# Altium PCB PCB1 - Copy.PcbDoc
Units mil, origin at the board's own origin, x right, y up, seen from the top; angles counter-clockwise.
Board outline 2362.2 x 3937.01 mil, 4 copper layers (Signal 1, GND 1, GND 2, Signal 2), stack 23.756 mil thick; 36 components, 44 nets, 223 pads, 235 vias.
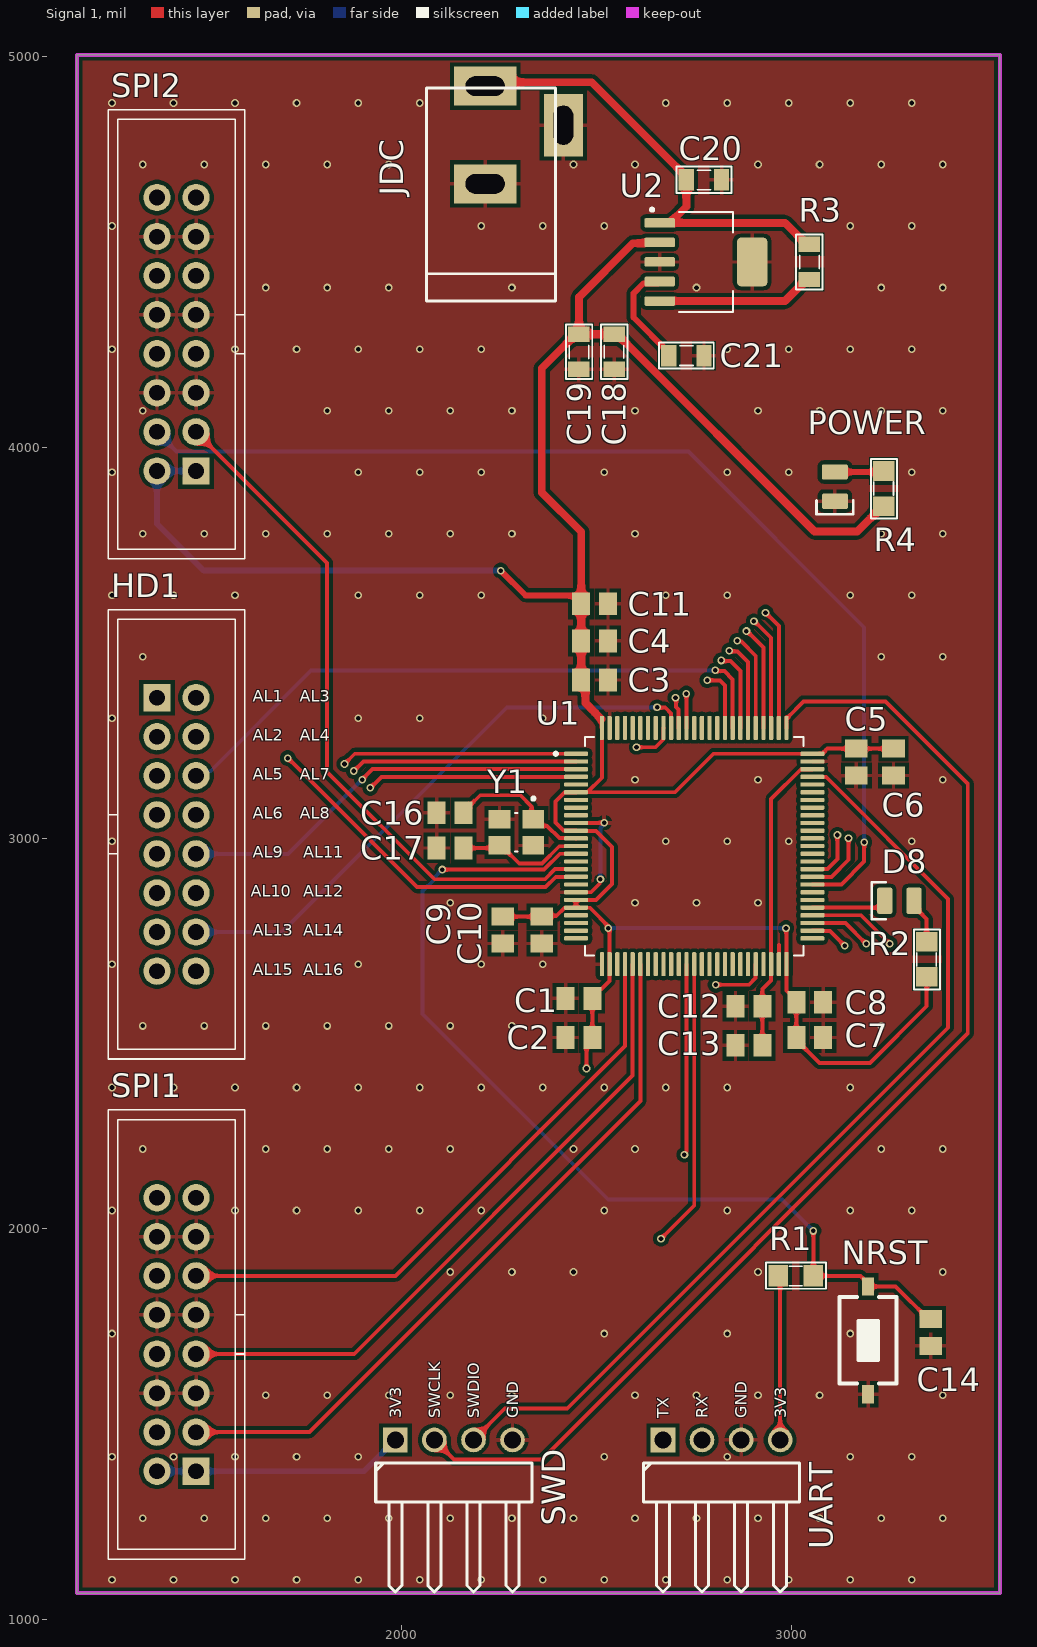
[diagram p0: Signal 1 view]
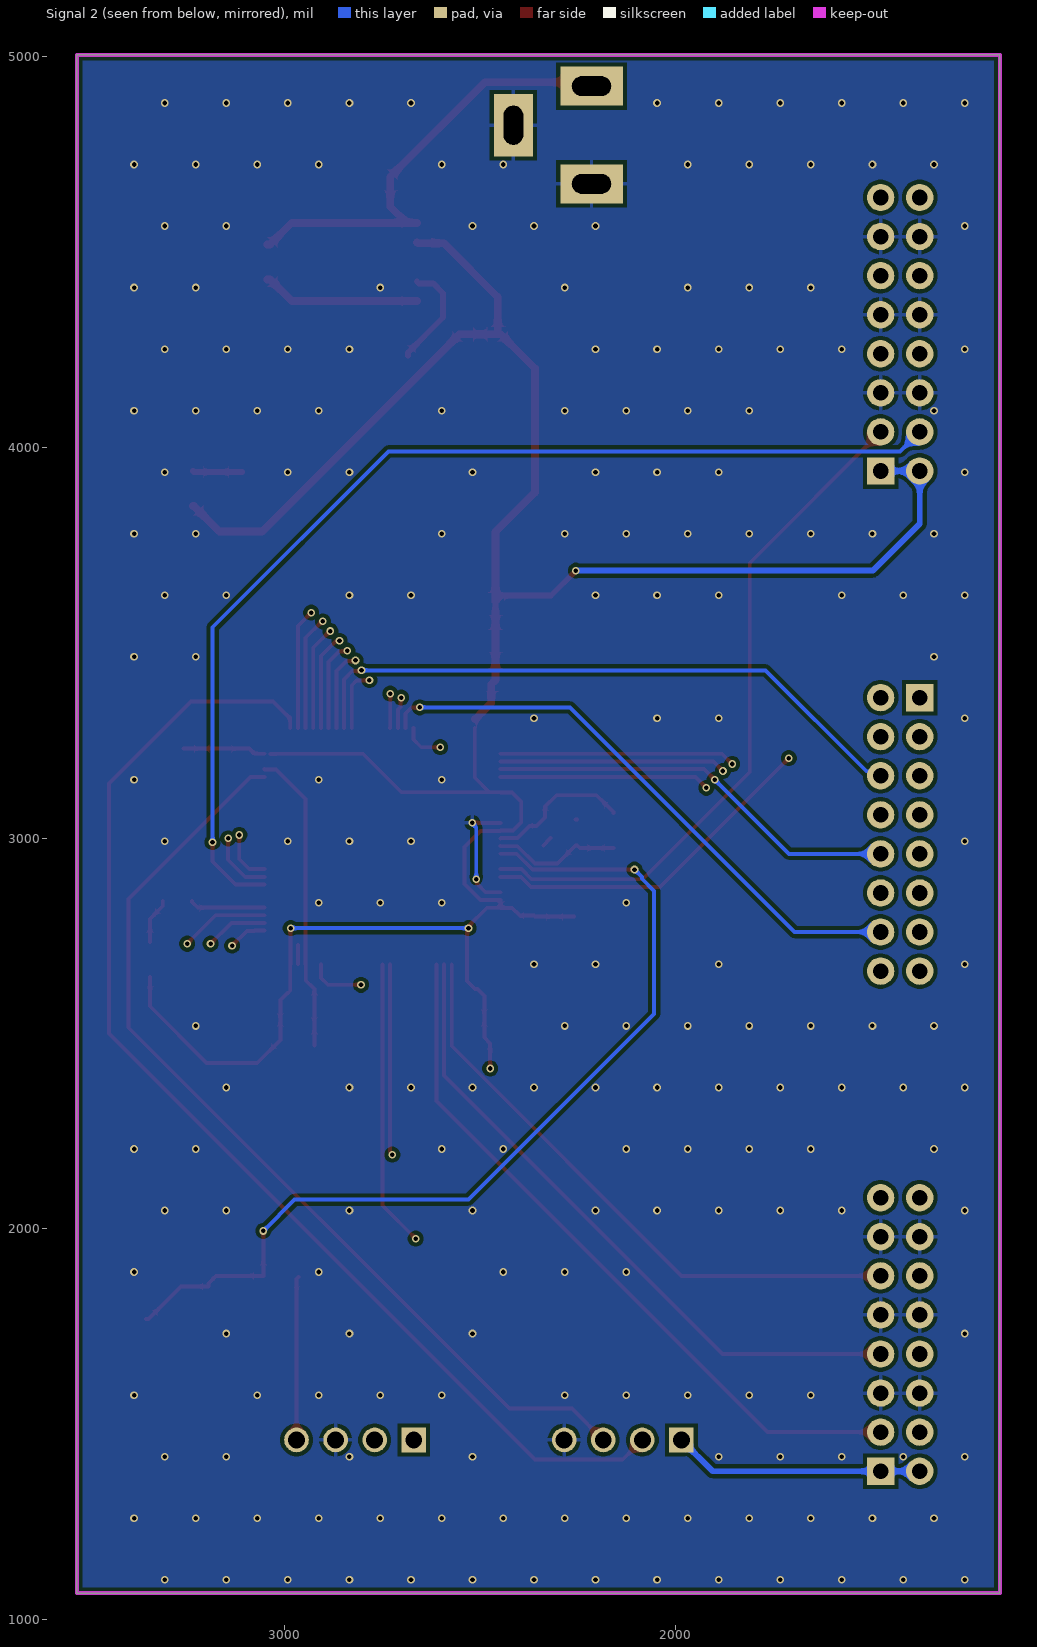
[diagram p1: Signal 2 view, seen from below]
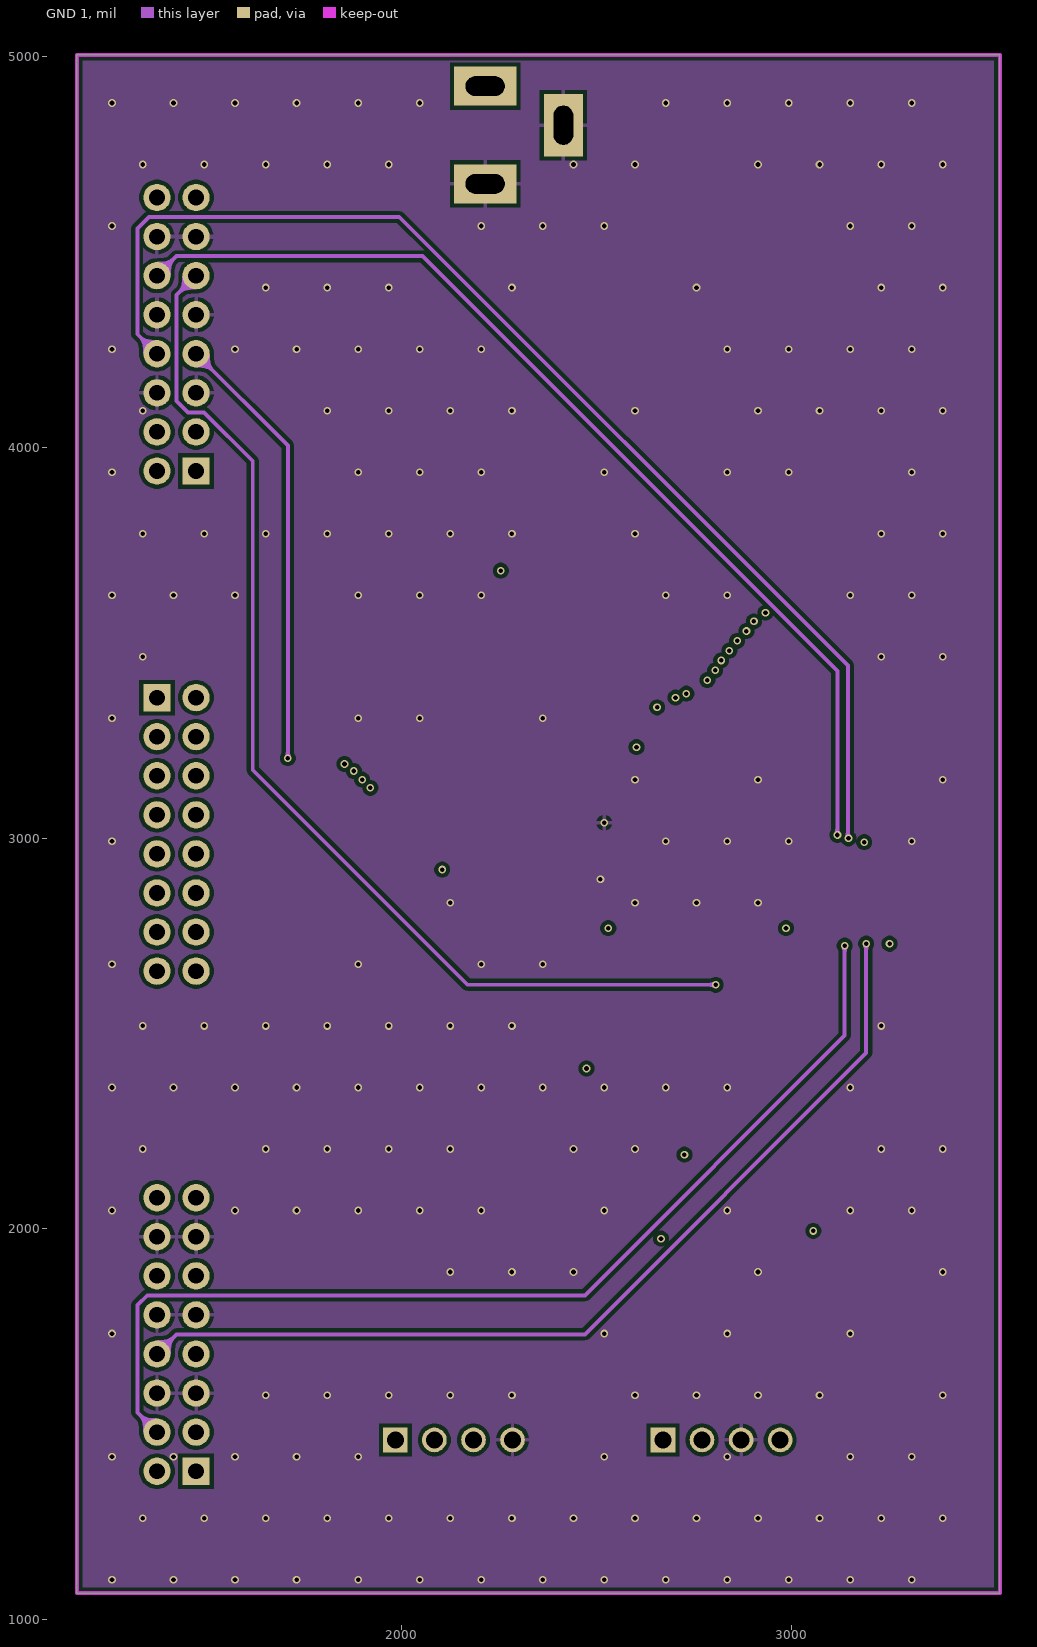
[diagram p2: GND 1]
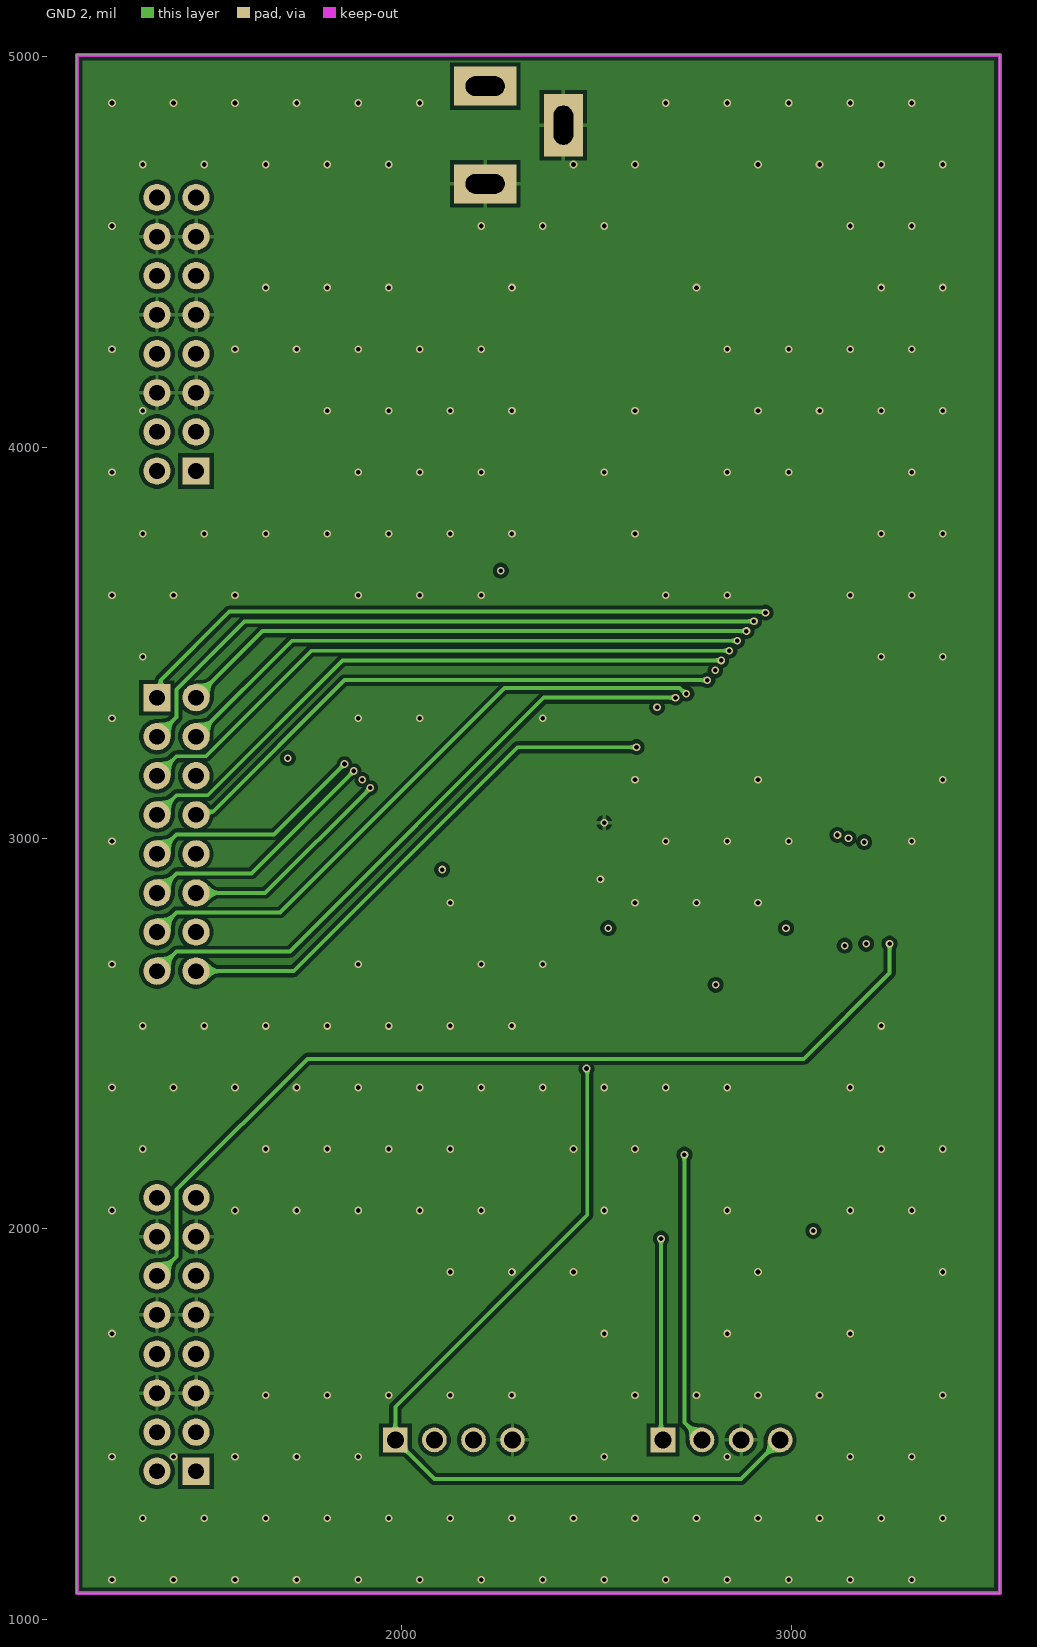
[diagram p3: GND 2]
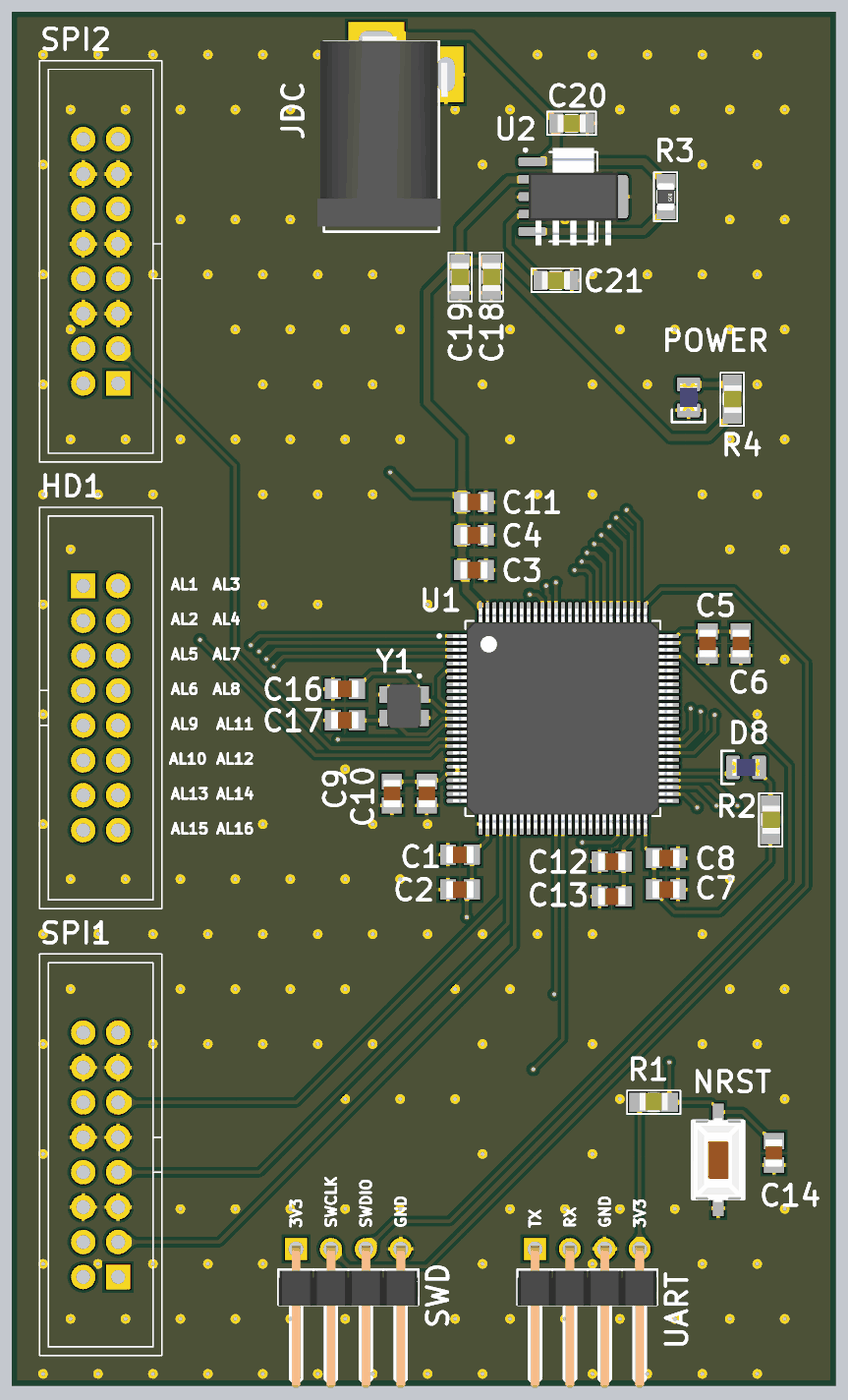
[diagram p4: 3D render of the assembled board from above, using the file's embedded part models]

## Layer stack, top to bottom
Top Solder: solder mask 0.4, Solder Resist, Dk 3.5
Signal 1: signal copper 1.378
Dielectric 2: prepreg 2.8, PP-006, Dk 4.1
GND 1: signal copper 1.4
Dielectric 1: dielectric 12.6, FR-4, Dk 4.8
GND 2: signal copper 1.4
Dielectric 3: prepreg 2.8, PP-006, Dk 4.1
Signal 2: signal copper 1.378
Bottom Solder: solder mask 0.4, Solder Resist, Dk 3.5

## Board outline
1170,1067.99 1170,5005 3532.2,5005 3532.2,1067.99

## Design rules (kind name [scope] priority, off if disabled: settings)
Clearance [All] p1: gap=10 ignorepadtopadclearanceinfootprint=TRUE except(5: Arc-Arc Arc-Track Arc-SMDPad Track-Track Track-SMDPad SMDPad-SMDPad)
PolygonConnect [All] p1: connectstyle=Relief reliefconductorwidth=10 reliefentries=4 polygonreliefangle="90 Angle" airgapwidth=10
RoutingVias [All] p1: holewidth=11.81 width=19.68 viastyle="Through Hole" minholewidth=7.87 minwidth=11.81 maxholewidth=28 maxwidth=50.28
SolderMaskExpansion [All] p1: expansion=4 istentingtop=FALSE
UnRoutedNet [All] p1: checkbadconnections=TRUE
Width [All] p1: maxlimit=50 minlimit=10 preferedwidth=10 minimp=50.000000 maximp=50.000000 favimp=50.000000
29 further rules are at their usual default settings.

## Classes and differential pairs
component class POWER: C18 C19 C20 C21 JDC POWER R3 R4 U2
component class MCU: C1 C2 C3 C4 C5 C6 C7 C8 C9 C10 C11 C12 C13 C14 C16 C17 D8 HD1 NRST R1 R2 SPI1 spi1 SPI2 SWD U1 UART Y1

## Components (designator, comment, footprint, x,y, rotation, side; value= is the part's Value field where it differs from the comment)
C1 "100nF" CAPC2012X145N 2455,2590 r0 top
C2 "100nF" CAPC2012X145N 2455,2490 r0 top
C3 "100nF" CAPC2012X145N 2495,3405 r180 top
C4 "100nF" CAPC2012X145N 2495,3505 r180 top
C5 "100nF" CAPC2012X145N 3165,3195 r90 top
C6 "100nF" CAPC2012X145N 3260,3195 r90 top
C7 "100nF" CAPC2012X145N 3045.71,2490 r180 top
C8 "100nF" CAPC2012X145N 3045.71,2580 r180 top
C9 "100nF" CAPC2012X145N 2260,2765 r90 top
C10 "100nF" CAPC2012X145N 2360,2765 r90 top
C11 "4.7uF" CAPC2012X145N 2495,3600 r180 top
C12 "2.2uF" CAPC2012X145N 2890,2570 r0 top
C13 "2.2uF" CAPC2012X145N 2890,2470 r0 top
C14 "100nF" CAPC2012X145N 3355,1735 r90 top
C16 "10pF" CAPC2012X145N 2125,3065 r0 top
C17 "10pF" CAPC2012X145N 2125,2975 r0 top
C18 "1uF" CAP_0805 2545,4245 r90 top value=33p
C19 "1uF" CAP_0805 2455,4245 r90 top value=33p
C20 "1uF" CAP_0805 2775,4685 r180 top value=33p
C21 "1uF" CAP_0805 2730,4235 r180 top value=33p
D8 "BLUE" LED_0805_BLUE 3275,2840 r0 top
HD1 "IDC 8X2" IDC16 1375,3360 r270 top value="Header 5x2"
JDC "Jac DC" DC-IN 2315,4800 r90 top
NRST "SW-SMD" SW-SMD 3195,1715 r270 top
POWER "BLUE" LED_0805_BLUE 3110,3900 r90 top
R1 "10K" SM-0805 3010,1880 r180 top value=1K
R2 "1K" SM-0805 3345,2690 r90 top
R3 "0R" RES-SMD-0805 3045,4475 r270 top
R4 "1K" SM-0805 3235,3895 r90 top
SPI1 "IDC 8X2" IDC16 1475,1380 r90 top value="Header 5x2"
SPI2 "IDC 8X2" IDC16 1475,3940 r90 top value="Header 5x2"
SWD "JP4" JP4-D1C 2335,1360 r0 top
U1 "STM32H743VIT6" QFP50P1600X1600X160-100N 2750,2980 r0 top
U2 "TPS73733DCQ" SOT127P706X180-6N 2780,4475 r0 top
UART "JP4" JP4-D1C 3020,1360 r0 top
Y1 "25MHz" XTAL_ABM8G-25.000MHZ-B4Y-T 2295,3015 r270 top

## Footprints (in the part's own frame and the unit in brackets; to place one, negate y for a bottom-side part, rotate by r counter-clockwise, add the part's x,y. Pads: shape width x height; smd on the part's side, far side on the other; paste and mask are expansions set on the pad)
CAP_0805 [mil]
  rect 39.37x55 smd: 1(-45,0) 2(45,0)
  silkscreen extent -70,-34 70,33, body extent -40,-25 40,25, height 24
CAPC2012X145N [mm]
  rect 1.17x1.47 smd: 1(-0.871,0) 2(0.871,0)
  body extent -1,-0.63 1,0.63, height 1.45
DC-IN [mil] "Jac DC input"
  rect 100x160 hole 50 slot 100 at 90 deg: 1(125,100) 2(-125,100)
  rect 160x100 hole 50 slot 100 at 0 deg: 3(25,-100)
  silkscreen extent -425,-80 120,250, body extent -410,-105 134,269, height 434
IDC16 [mil]
  rect 70x70 hole 40: 1(0,0)
  round 70 hole 40: 2(0,100) 3(100,0) 4(100,100) 5(200,0) 6(200,100) 7(300,0) 8(300,100) 9(400,0) 10(400,100) 11(500,0) 12(500,100) 13(600,0) 14(600,100) 15(700,0) 16(700,100)
  silkscreen extent -225,-125 925,225, body extent -225,-125 926,225, height 358
JP4-D1C [mm] "4 pins, 1 row, right angled, gold plating"
  rect 1.6x1.6 hole 1.1: 1(-8.89,2.54)
  round 1.6 hole 1.1: 2(-6.35,2.54) 3(-3.81,2.54) 4(-1.27,2.54)
  silkscreen extent -10.16,-7.34 0,1.04, body extent -10.16,-7.57 0,2.79, height 2.54
LED_0805_BLUE [mm]
  rrect25% 1x1.7 smd: A(0.95,0) K(-0.95,0)
  silkscreen extent -1.8,-1.2 -0.9,1.2, body extent -1,-0.63 1,0.63, height 1.12
QFP50P1600X1600X160-100N [mm]
  rrect50% 1.56x0.28 smd: 1(-7.68,6) 2(-7.68,5.5) 3(-7.68,5) 4(-7.68,4.5) 5(-7.68,4) 6(-7.68,3.5) 7(-7.68,3) 8(-7.68,2.5) 9(-7.68,2) 10(-7.68,1.5) 11(-7.68,1) 12(-7.68,0.5) 13(-7.68,0) 14(-7.68,-0.5) 15(-7.68,-1) 16(-7.68,-1.5) 17(-7.68,-2) 18(-7.68,-2.5) 19(-7.68,-3) 20(-7.68,-3.5) 21(-7.68,-4) 22(-7.68,-4.5) 23(-7.68,-5) 24(-7.68,-5.5) 25(-7.68,-6) 51(7.68,-6) 52(7.68,-5.5) 53(7.68,-5) 54(7.68,-4.5) 55(7.68,-4) 56(7.68,-3.5) 57(7.68,-3) 58(7.68,-2.5) 59(7.68,-2) 60(7.68,-1.5) 61(7.68,-1) 62(7.68,-0.5) 63(7.68,0) 64(7.68,0.5) 65(7.68,1) 66(7.68,1.5) 67(7.68,2) 68(7.68,2.5) 69(7.68,3) 70(7.68,3.5) 71(7.68,4) 72(7.68,4.5) 73(7.68,5) 74(7.68,5.5) 75(7.68,6)
  rrect50% 0.28x1.56 smd: 26(-6,-7.68) 27(-5.5,-7.68) 28(-5,-7.68) 29(-4.5,-7.68) 30(-4,-7.68) 31(-3.5,-7.68) 32(-3,-7.68) 33(-2.5,-7.68) 34(-2,-7.68) 35(-1.5,-7.68) 36(-1,-7.68) 37(-0.5,-7.68) 38(0,-7.68) 39(0.5,-7.68) 40(1,-7.68) 41(1.5,-7.68) 42(2,-7.68) 43(2.5,-7.68) 44(3,-7.68) 45(3.5,-7.68) 46(4,-7.68) 47(4.5,-7.68) 48(5,-7.68) 49(5.5,-7.68) 50(6,-7.68) 76(6,7.68) 77(5.5,7.68) 78(5,7.68) 79(4.5,7.68) 80(4,7.68) 81(3.5,7.68) 82(3,7.68) 83(2.5,7.68) 84(2,7.68) 85(1.5,7.68) 86(1,7.68) 87(0.5,7.68) 88(0,7.68) 89(-0.5,7.68) 90(-1,7.68) 91(-1.5,7.68) 92(-2,7.68) 93(-2.5,7.68) 94(-3,7.68) 95(-3.5,7.68) 96(-4,7.68) 97(-4.5,7.68) 98(-5,7.68) 99(-5.5,7.68) 100(-6,7.68)
  silkscreen extent -9.1,-7.1 7.1,7.1, body extent -8,-8 8,8, height 1.6
RES-SMD-0805 [mil]
  rect 39.37x55 smd: 1(-45,0) 2(45,0)
  silkscreen extent -70,-34 70,33, body extent -39,-25 39,25, height 31
SM-0805 [mil] "Compoment SMD 80x50mil"
  rect 50x55 smd: 1(-45,0) 2(45,0)
  silkscreen extent -77,-34 76,33, body extent -40,-27 40,23, height 24
SOT127P706X180-6N [mm]
  rrect25% 1.97x0.62 smd: 1(-3.005,2.54) 2(-3.005,1.27) 3(-3.005,0) 4(-3.005,-1.27) 5(-3.005,-2.54)
  rrect25% 1.97x3.16 smd: 6(3.005,0)
  silkscreen extent -3.6,-3.25 1.75,3.5, body extent -3.25,-3.53 3.25,3.53, height 1.8
SW-SMD [mm] "Switch SMD type"
  rect 1.2x0.8 smd: 1(-3.5,0) 2(3.5,0)
  silkscreen extent -2.82,-1.85 2.82,1.85, body extent -3.05,-1.85 3.05,1.85, height 2.5
XTAL_ABM8G-25.000MHZ-B4Y-T [mm]
  rect 1.2x1.4 smd: 1(-0.85,1.1) 2(-0.85,-1.1) 3(0.85,-1.1) 4(0.85,1.1)
  silkscreen extent -2.3,-0.08 1.25,1.2, body extent -1.6,-1.24 1.6,1.24, height 0.99

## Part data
C1 C2 C3 C4 C5 C6 C7 C8 C9 C10 C12 C13 C14 C16 C17: library part VJ0805A390GXCAP, "39 pF Â±2% 200V Ceramic Capacitor C0G, NP0 0805 (2012 Metric)", Package="2012 Vishay Vitramon"
C11: library part CAP_TAN_SMD, "Polazied Tantalum Capacitor"
C18 C19 C20 C21: library part CapSMD, "Capacitor"
D8 POWER: library part LED_0805_BLUE, "LED 0805 BLUE SMD"
HD1 SPI1 SPI2: library part "IDC 8x2"
JDC: library part DCIN, "Jac DC input"
NRST: "Switch"
R1 R2 R4: library part RM, "Resistor SMD"
R3: library part "Resistor - SMD", "Resistor SMD", Manufacturer="Generic Components"
SWD UART: "WR-PHD 2.54 mm Angled Socket Header", Manufacturer="W¨¹rth Elektronik eiSos GmbH", partNo=613004143121
U1: "ARMÂ® CortexÂ®-M7 STM32H7 Microcontroller IC 32-Bit Single-Core 480MHz 2MB (2M x 8) FLASH 100-LQFP (14x14)", Package="LQFP-100 STMicroelectronics"
U2: "1-A, ultra-low-dropout voltage regulator with reverse current protection & enable", Package="SOT-223-6 Texas Instruments"
Y1: library part ABM8G-25.000MHZ-B4Y-T, "25 MHz Â±30ppm Crystal 10pF 60 Ohms 4-SMD, No Lead", Package="SMD-4 Abracon"

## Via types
v1: diameter 19.68, hole 11.81, Signal 1 to Signal 2, 201 vias
v2: diameter 19.68, hole 11.81, Signal 1 to Signal 2, tented top, 34 vias

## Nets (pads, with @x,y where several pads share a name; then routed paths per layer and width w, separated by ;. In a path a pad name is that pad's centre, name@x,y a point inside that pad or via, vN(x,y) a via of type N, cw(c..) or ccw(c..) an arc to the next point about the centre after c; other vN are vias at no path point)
3V3: C1.2 C2.2 C3.2 C4.2 C5.2 C6.2 C7.2 C8.2 C9.2 C10.2 C11.2 C18.2 C19.2 R1.2 R2.1 R4.1 SPI1.1 SPI1.2 SPI2.1 SPI2.2 SWD.1 U1.6 U1.11 U1.20 U1.21 U1.27 U1.50 U1.75 U1.100 U2.2 UART.4 | length 10641.6
  Signal 1 w10: C9.2 C10.2 2362.73,2802.02 2398.08,2802.02 2418.06,2822.01 U1.21@2448.1,2822.01 ; U1.11@2447.13,3019.88 2415.88,3019.88 2395,3040.76 2395,3094.22 2418.06,3117.28 2447.13,3117.28 U1.6 2701.04,3117.8 2799.47,3216.22 3036.81,3216.22 3037.32,3215.71 U1.75@3022.79,3215.71 ; U1.21 U1.20 2498.83,2842.2 2540,2883.37 2540,2977.7 2498.84,3018.86 2448.15,3018.86 U1.11@2448.05,3018.96 ; U1.21@2448.13,2822.03 2482.97,2822.03 2533.46,2771.54 U1.27 2533.46,2634.17 2513.23,2613.94 2507.32,2613.94 2489.29,2595.91 C1.2 C2.2 2474.39,2475.1 v2(2474.39,2410.61) ; U1.6@2477.21,3118.31 2513.78,3154.87 U1.100 ; R1.2@2965,1877.5 2970,1872.5 UART.4 ; v2(2985,2770) 2985.71,2769.29 2985.71,2678.15 U1.50 2986.22,2609.79 2992.08,2603.94 2993.39,2603.94 3011.42,2585.91 C8.2 C7.2 3011.42,2484.09 3070.51,2425 3200,2425 3345,2570 R2.1 ; U1.75 3077.56,3216.22 3090.63,3229.29 C5.2 C6.2
  Signal 1 w15: v2(2255,3685) 2318.56,3621.44 2445.18,3621.44 2460.71,3605.91 C11.2 C11.2@2460.71,3580
  Signal 1 w20: C11.2@2460.71,3580 C4.2 C3.2 2471.89,3393.82 2471.89,3346.06 U1.100@2512.95,3305 ; C11.2@2460.71,3605.91 2460.71,3784.29 2360,3885 2360,4202.81 2447.19,4290 C19.2 ; U2.2 2659.49,4522.8 2592.8,4522.8 2455,4385 C19.2 ; R4.1 3232.5,3850 3167.5,3785 3057.81,3785 2552.81,4290 C18.2 C19.2
  GND 2 w10: v2(2474.39,2410.61) 2476.25,2408.75 2476.25,2036.25 1985,1545 SWD.1 2085,1360 2870,1360 UART.4
  Signal 2 w10: v2(2530,2770) v2(2985,2770)
  Signal 2 w15: SPI1.2 SPI1.1 1905,1380 SWD.1 ; SPI2.1 SPI2.2 1375,3805 1495,3685 v2(2255,3685)
5V: C20.2 JDC.1 R3.1 U2.1 | length 1160.6
  Signal 1 w10: C20.2 C20.2@2730,4692.81
  Signal 1 w20: JDC.1 2225,4935 2487.82,4935 C20.2@2730,4692.81 ; U2.1 U2.1@2688.27,4575 ; C20.2 2730,4616.73 U2.1@2688.27,4575 ; R3.1 3037.19,4520 2982.19,4575 U2.1@2688.27,4575
A1: SPI1.4 U1.52 | length 2770.1
  Signal 1 w10: U1.52 3077.56,2763.46 3078.07,2762.95 3097.05,2762.95 v2(3135,2725)
  GND 1 w10: SPI1.4 1325,1530 1325,1805 1350,1830 2470,1830 3135,2495 v2(3135,2725)
A2: SPI2.4 U1.58 | length 2773.9
  Signal 1 w10: U1.58 3126.57,2881.57 3185,2940 v2(3185,2990)
  Signal 2 w10: SPI2.4 1425,3990 1454.29,3990 1495.71,3990 2735,3990 3185,3540 v2(3185,2990)
AL1: HD1.1 U1.77 | length 1979.3
  Signal 1 w10: v2(2932.43,3577.43) 2966.54,3543.33 U1.77
  GND 2 w10: HD1.1 1384.14,3369.14 1384.14,3404.14 1560,3580 2923.02,3580 2923.73,3579.29 2930.58,3579.29 v2(2932.43,3577.43)
AL2: HD1.3 U1.78 | length 1983.8
  Signal 1 w10: v2(2902.86,3555.16) 2904.98,3555.16 2946.85,3513.28 U1.78
  GND 2 w10: HD1.3 1425,3310 1425,3380.71 1599.45,3555.16 v2(2902.86,3555.16)
AL3: HD1.2 U1.79 | length 1745.9
  Signal 1 w10: v2(2883.66,3530.32) 2884.82,3530.32 2927.17,3487.97 U1.79
  GND 2 w10: HD1.2 1645.31,3530.32 v2(2883.66,3530.32)
AL4: HD1.4 U1.80 | length 1734.7
  Signal 1 w10: v2(2859.97,3505.47) 2861.82,3503.62 2870.79,3503.62 2907.48,3466.92 U1.80
  GND 2 w10: HD1.4 1720.47,3505.47 v2(2859.97,3505.47)
AL5: HD1.5 U1.81 | length 1826.3
  Signal 1 w10: v2(2840,3480) 2841.85,3478.15 2861.13,3478.15 2887.8,3451.48 U1.81
  GND 2 w10: HD1.5 1425,3210 1500,3210 1770,3480 v2(2840,3480)
AL6: HD1.7 U1.82 | length 1813.6
  Signal 1 w10: v2(2819.01,3455.16) 2820.86,3453.3 2842.62,3453.3 2868.11,3427.81 U1.82
  GND 2 w10: HD1.7 1425,3110 1505,3110 1850.16,3455.16 v2(2819.01,3455.16)
AL7: HD1.6 U1.83 | length 1619
  Signal 1 w10: v2(2803.84,3429.64) 2805.7,3427.79 2827.41,3427.79 2848.43,3406.77 U1.83
  Signal 2 w10: HD1.6 1486.48,3171.48 1511.48,3171.48 1769.64,3429.64 v2(2803.84,3429.64)
AL8: HD1.8 U1.84 | length 1611.1
  Signal 1 w10: v2(2783.45,3404.8) 2784.31,3403.93 2816.07,3403.93 2828.74,3391.26 U1.84
  GND 2 w10: HD1.8 1482.86,3067.86 1517.86,3067.86 1854.8,3404.8 v2(2783.45,3404.8)
AL9: HD1.9 U1.1 | length 1178.8
  Signal 1 w10: v2(1855,3190) 1881.22,3216.22 U1.1
  GND 2 w10: HD1.9 1425,3010 1525,3010 1675,3010 v2(1855,3190)
AL10: HD1.11 U1.2 | length 1212
  Signal 1 w10: v2(1878.75,3172.19) 1903.09,3196.54 U1.2
  GND 2 w10: HD1.11 1425,2910 1616.56,2910 v2(1878.75,3172.19)
AL11: HD1.10 U1.3 | length 1062.5
  Signal 1 w10: v2(1900,3150) 1926.85,3176.85 U1.3
  Signal 2 w10: HD1.10 1710,2960 v2(1900,3150)
AL12: HD1.12 U1.4 | length 1095.7
  Signal 1 w10: v2(1920.99,3129.01) 1949.15,3157.17 U1.4
  GND 2 w10: HD1.12 1651.98,2860 v2(1920.99,3129.01)
AL13: HD1.13 U1.89 | length 1707.7
  Signal 1 w10: v2(2730,3370) 2730.16,3369.84 2730.16,3282.52 U1.89
  GND 2 w10: HD1.13 1425,2810 1690,2810 2264.36,3384.36 2638.01,3384.36 2638.5,3384.84 2712.54,3384.84 2727.38,3370 v2(2730,3370)
AL14: HD1.15 U1.90 | length 1698.2
  Signal 1 w10: v2(2702.05,3360) 2703.9,3358.15 2703.9,3336.08 2710.31,3329.67 2710.31,3282.68 U1.90
  GND 2 w10: HD1.15 1425,2710 1715,2710 2365,3360 v2(2702.05,3360)
AL15: HD1.14 U1.91 | length 1497.5
  Signal 1 w10: v2(2655,3335.16) 2655.98,3334.17 2675.83,3334.17 2690.94,3319.06 U1.91
  Signal 2 w10: HD1.14 1695,2760 2270.16,3335.16 v2(2655,3335.16)
AL16: HD1.16 U1.92 | length 1471.1
  Signal 1 w10: v2(2602.36,3232.95) 2650.91,3232.95 2670.75,3252.79 2670.75,3281.85 U1.92
  GND 2 w10: HD1.16 1725,2660 2297.95,3232.95 v2(2602.36,3232.95)
B1: SPI1.8 U1.53 | length 2573.6
  Signal 1 w10: U1.53 3136.85,2783.15 v2(3190,2730)
  GND 1 w10: SPI1.8 1425,1730 2470,1730 3190,2450 v2(3190,2730)
B2: SPI2.8 U1.59 | length 3255.7
  Signal 1 w10: U1.59 3101.26,2901.26 3145,2945 v2(3145,3000)
  GND 1 w10: SPI2.8 1325,4290 1325,4560.71 1354.29,4590 1995,4590 3143.15,3441.85 3143.15,3001.85 v2(3145,3000)
C1: SPI1.12 U1.54 | length 2598.8
  Signal 1 w10: U1.54 3177.17,2802.83 v2(3250,2730)
  GND 2 w10: SPI1.12 1425,1930 1425,2100.71 1759.74,2435.45 3030.45,2435.45 3250,2655 v2(3250,2730)
C2: SPI2.12 U1.60 | length 2758.7
  Signal 1 w10: U1.60 3090.94,2920.94 3116.54,2946.54 v2(3116.54,3008.46)
  GND 1 w10: SPI2.12 1425,4490 2055,4490 3116.54,3428.46 v2(3116.54,3008.46)
GND: C1.1 C2.1 C3.1 C4.1 C5.1 C6.1 C7.1 C8.1 C9.1 C10.1 C11.1 C12.1 C13.1 C14.1 C16.1 C17.1 C18.1 C19.1 C20.1 C21.1 JDC.2 JDC.3 NRST.2 POWER.K SPI1.5 SPI1.6 SPI1.9 SPI1.10 SPI1.13 SPI1.14 SPI2.5 SPI2.6 SPI2.9 SPI2.10 SPI2.13 SPI2.14 SWD.4 U1.10 U1.19 U1.26 U1.49 U1.74 U1.99 U2.3 U2.6 UART.3 Y1.2 Y1.4 | length 382.4
  Signal 1 w10: Y1.2 Y1.2@2255.63,3048.46 ; Y1.4@2319.68,3000.16 Y1.4 ; U1.19 2485.94,2861.89 2508.15,2884.09 2508.15,2893.15 v2(2510,2895) ; U1.10 2448.11,3039.53 2519.53,3039.53 v2(2520,3040) ; U1.49 2966.54,2726.54
  Signal 2 w10: v2(2510,2895) 2510,3027.38 2520,3037.38 v2(2520,3040)
  other v1: 1259.84,1102.36 1417.32,1102.36 1574.8,1102.36 1732.28,1102.36 1889.76,1102.36 2047.24,1102.36 2204.72,1102.36 2362.2,1102.36 2519.68,1102.36 2677.17,1102.36 2834.65,1102.36 2992.13,1102.36 3149.61,1102.36 3307.09,1102.36 1338.58,1259.84 1496.06,1259.84 1653.54,1259.84 1811.02,1259.84 1968.5,1259.84 2125.98,1259.84 2283.46,1259.84 2440.94,1259.84 2598.42,1259.84 2755.91,1259.84 2913.39,1259.84 3070.87,1259.84 3228.35,1259.84 3385.83,1259.84 1259.84,1417.32 1417.32,1417.32 1574.8,1417.32 1732.28,1417.32 1889.76,1417.32 2519.68,1417.32 2834.65,1417.32 3149.61,1417.32 3307.09,1417.32 1653.54,1574.8 1811.02,1574.8 1968.5,1574.8 2125.98,1574.8 2283.46,1574.8 2598.42,1574.8 2755.91,1574.8 2913.39,1574.8 3070.87,1574.8 3385.83,1574.8 1259.84,1732.28 2519.68,1732.28 2834.65,1732.28 3149.61,1732.28 2125.98,1889.76 2283.46,1889.76 2440.94,1889.76 2913.39,1889.76 3385.83,1889.76 1259.84,2047.24 1574.8,2047.24 1732.28,2047.24 1889.76,2047.24 2047.24,2047.24 2204.72,2047.24 2519.68,2047.24 2834.65,2047.24 3149.61,2047.24 3307.09,2047.24 1338.58,2204.72 1653.54,2204.72 1811.02,2204.72 1968.5,2204.72 2125.98,2204.72 2440.94,2204.72 2598.42,2204.72 3228.35,2204.72 3385.83,2204.72 1259.84,2362.2 1417.32,2362.2 1574.8,2362.2 1732.28,2362.2 1889.76,2362.2 2047.24,2362.2 2204.72,2362.2 2362.2,2362.2 2519.68,2362.2 2677.17,2362.2 2834.65,2362.2 3149.61,2362.2 1338.58,2519.68 1496.06,2519.68 1653.54,2519.68 1811.02,2519.68 1968.5,2519.68 2125.98,2519.68 2283.46,2519.68 3228.35,2519.68 1259.84,2677.17 1889.76,2677.17 2204.72,2677.17 2362.2,2677.17 2125.98,2834.65 2598.42,2834.65 2755.91,2834.65 2913.39,2834.65 1259.84,2992.13 2677.17,2992.13 2834.65,2992.13 2992.13,2992.13 3307.09,2992.13 2598.42,3149.61 2913.39,3149.61 3385.83,3149.61 1259.84,3307.09 1889.76,3307.09 2047.24,3307.09 2362.2,3307.09 1338.58,3464.57 3228.35,3464.57 3385.83,3464.57 1259.84,3622.05 1417.32,3622.05 1574.8,3622.05 1889.76,3622.05 2047.24,3622.05 2204.72,3622.05 2677.17,3622.05 2834.65,3622.05 3149.61,3622.05 3307.09,3622.05 1338.58,3779.53 1496.06,3779.53 1653.54,3779.53 1811.02,3779.53 1968.5,3779.53 2125.98,3779.53 2283.46,3779.53 2598.42,3779.53 3228.35,3779.53 3385.83,3779.53 1259.84,3937.01 1889.76,3937.01 2047.24,3937.01 2204.72,3937.01 2519.68,3937.01 2834.65,3937.01 2992.13,3937.01 3307.09,3937.01 1338.58,4094.49 1811.02,4094.49 1968.5,4094.49 2125.98,4094.49 2283.46,4094.49 2598.42,4094.49 2913.39,4094.49 3070.87,4094.49 3228.35,4094.49 3385.83,4094.49 1259.84,4251.97 1574.8,4251.97 1732.28,4251.97 1889.76,4251.97 2047.24,4251.97 2204.72,4251.97 2834.65,4251.97 2992.13,4251.97 3149.61,4251.97 3307.09,4251.97 1653.54,4409.45 1811.02,4409.45 1968.5,4409.45 2283.46,4409.45 2755.91,4409.45 3228.35,4409.45 3385.83,4409.45 1259.84,4566.93 2204.72,4566.93 2362.2,4566.93 2519.68,4566.93 3149.61,4566.93 3307.09,4566.93 1338.58,4724.41 1496.06,4724.41 1653.54,4724.41 1811.02,4724.41 1968.5,4724.41 2440.94,4724.41 2598.42,4724.41 2913.39,4724.41 3070.87,4724.41 3228.35,4724.41 3385.83,4724.41 1259.84,4881.89 1417.32,4881.89 1574.8,4881.89 1732.28,4881.89 1889.76,4881.89 2047.24,4881.89 2677.17,4881.89 2834.65,4881.89 2992.13,4881.89 3149.61,4881.89 3307.09,4881.89
HSE_IN: C16.2 U1.12 Y1.1 | length 370.4
  Signal 1 w10: C16.2 2159.29,3066.97 2202.32,3110 2305,3110 2333.77,3081.23 2333.77,3053 2355.39,3031.38 2373.62,3031.38 2404.8,3000.2 2447.13,3000.2 U1.12
HSE_OUT: C17.2 U1.13 Y1.3 | length 330.1
  Signal 1 w10: C17.2@2158.46,2975.83 C17.2 2245.16,2975 Y1.3 2255.63,2981.54 2302.17,2935 2360,2935 2404.49,2979.49 2447.13,2979.49 U1.13
LED: D8.K U1.55 | length 194.1
  Signal 1 w10: U1.55 3222.91,2822.52 3237.6,2837.2 D8.K
NetC21_2: C21.2 U2.4 | length 276.4
  Signal 1 w15: U2.4 2656.99,4420.3 2620.3,4420.3 2595,4395 2595,4332.82 2685,4242.81 C21.2
NetD8_A: D8.A R2.2 | length 118.5
  Signal 1 w10: D8.A 3312.4,2826.22 3345,2793.62 R2.2
NetPOWER_A: POWER.A R4.2 | length 126.1
  Signal 1 w15: POWER.A 3232.4,3937.4 R4.2
NetR3_2: R3.2 U2.5 | length 406.1
  Signal 1 w20: U2.5 2982.18,4375 3037.19,4430 R3.2
NRST: C14.2 NRST.1 R1.1 U1.14 | length 2445.3
  Signal 1 w10: v2(2105,2919.84) 2366.06,2919.84 2406.53,2960.32 U1.14 ; v2(3055,1995) R1.1 3175.67,1880 3195,1860.67 NRST.1 3265.59,1852.8 3349.09,1769.29 C14.2
  Signal 2 w10: v2(2105,2919.84) 2086.32,2901.16 2086.32,2896.32 2055,2865 2055,2550 2530,2075 2975,2075 v2(3055,1995)
RX: U1.37 UART.2 | length 1238.5
  Signal 1 w10: v2(2725,2190) 2725,2192.62 2730.32,2197.94 U1.37
  GND 2 w10: v2(2725,2190) 2725,1505 UART.2
SPI1_MISO: SPI1.7 U1.30 | length 1697.8
  Signal 1 w10: SPI1.7 1880,1680 2592.52,2392.52 U1.30
SPI1_MOSI: SPI1.3 U1.31 | length 1838.6
  Signal 1 w10: SPI1.3 1765,1480 2612.2,2327.2 U1.31
SPI1_SCK: SPI1.11 U1.29 | length 1551.1
  Signal 1 w10: SPI1.11 1985,1880 2572.83,2467.83 U1.29
SPI2_MISO: SPI2.7 U1.17 | length 2017.5
  Signal 1 w10: v2(1710,3205) 2040,2875 2369.46,2875 2395.72,2901.26 U1.17
  GND 1 w10: SPI2.7 1710,4005 v2(1710,3205)
SPI2_MOSI: SPI2.3 U1.16 | length 1771.1
  Signal 1 w10: SPI2.3 1810,3705 1810,3170 2085,2895 2368.25,2895 2394.19,2920.94 U1.16
SPI2_SCK: SPI2.11 U1.46 | length 2948.4
  Signal 1 w10: v2(2805,2625) 2890,2625 2907.15,2642.15 2907.15,2677.31 U1.46
  GND 1 w10: SPI2.11 1425,4390 1425,4296.53 1425,4170 1425,4150 1425,4119.29 1454.29,4090 1495.71,4090 1620,3965.71 1620,3175 2170,2625 v2(2805,2625)
SWCLK: SWD.2 U1.76 | length 3070.7
  Signal 1 w10: SWD.2 2135,1410 2360,1410 3450,2500 3450,3140 3240,3350 3030,3350 2988.07,3308.07 2986.73,3308.07 2986.22,3307.56 U1.76
SWDIO: SWD.3 U1.72 | length 2458.9
  Signal 1 w10: SWD.3 2265,1540 2425,1540 3400,2515 3400,2845 3088.01,3156.99 3052.54,3156.99 U1.72
TX: U1.38 UART.1 | length 1254.9
  Signal 1 w10: v2(2665,1975) 2750,2060 U1.38
  GND 2 w10: v2(2665,1975) 2665,1465 UART.1
VCAP: C12.2 C13.2 U1.48 U1.73 | length 776.9
  Signal 1 w10: C13.2 C12.2 2924.29,2613.94 2946.34,2635.98 2946.34,2677.13 U1.48 2946.85,3100.4 3022.79,3176.34 3051.85,3176.34 U1.73
pads on no net: SPI1.15 SPI1.16 SPI2.15 SPI2.16 U1.5 U1.7 U1.8 U1.9 U1.15 U1.18 U1.22 U1.23 U1.24 U1.25 U1.28 U1.32 U1.33 U1.34 U1.35 U1.36 U1.39 U1.40 U1.41 U1.42 U1.43 U1.44 U1.45 U1.47 U1.51 U1.56 U1.57 U1.61 U1.62 U1.63 U1.64 U1.65 U1.66 U1.67 U1.68 U1.69 U1.70 U1.71 U1.85 U1.86 U1.87 U1.88 U1.93 U1.94 U1.95 U1.96 U1.97 U1.98

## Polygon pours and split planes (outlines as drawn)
GND on Signal 2 "GND_L04_P004" (solid, remove dead copper, pour order 4): 941.17,5020.88 951.17,5010.88 3536.17,5010.88 3536.17,980.88 3436.17,880.88 3411.17,905.88 1021.17,905.88 1021.17,5005.88 1036.17,5020.88
GND on GND 1 "GND_L02_P001" (solid, remove dead copper, pour order 1): 1094.71,5008.98 1139.71,5053.98 3724.71,5053.98 3724.71,908.98 3654.71,838.98 1019.71,838.98 1019.71,4938.98 1099.71,5018.98
GND on GND 2 "GND_L03_P003" (solid, pour order 3): 3530.96,1075 3525.96,1080 3525.96,5005 1160.96,5005 1165.96,5000 1165.96,1070 3525.96,1070
GND on Signal 1 "GND_L01_P000" (solid, pour order 0): 1179.71,5011.48 1189.71,5001.48 3529.71,5001.48 3529.71,1061.48 3519.71,1071.48 1169.71,1071.48 1169.71,4996.48 1174.71,5001.48

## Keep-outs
Keep-Out Layer:
  the board outline again, w10

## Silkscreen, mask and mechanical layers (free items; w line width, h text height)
Top Overlay:
  text "AL1" at 1620,3350 h30
  text "AL3" at 1740,3350 h30
  text "AL2" at 1620,3250 h30
  text "AL4" at 1740,3250 h30
  text "AL5" at 1620,3150 h30
  text "AL7" at 1740,3150 h30
  text "AL6" at 1620,3050 h30
  text "AL8" at 1740,3050 h30
  text "AL9" at 1620,2950 h30
  text "AL11" at 1750,2950 h30
  text "AL10" at 1615,2850 h30
  text "AL12" at 1750,2850 h30
  text "AL13" at 1620,2750 h30
  text "AL14" at 1750,2750 h30
  text "AL15" at 1620,2650 h30
  text "AL16" at 1750,2650 h30
  text "3V3" at 2000,1515 h30 r90
  text "SWCLK" at 2100,1515 h30 r90
  text "SWDIO" at 2200,1515 h30 r90
  text "GND" at 2300,1515 h30 r90
  text "TX" at 2684.99,1515 h30 r90
  text "RX" at 2784.99,1515 h30 r90
  text "GND" at 2885,1515 h30 r90
  text "3V3" at 2985,1515 h30 r90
